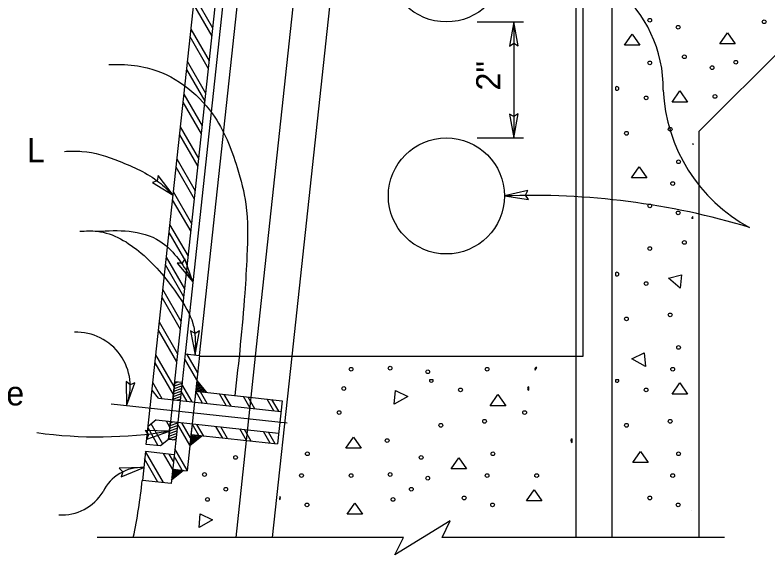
# Model space of a CAD drawing. Extents: x 0 to 2.83, y -0.03 to 1.83.
# Drawn here: x 2.1899 to 2.5956, y 0.3171 to 0.6079 of the extents above; entities that cross this region are included whole.
import ezdxf

# ---------------------------------------------------------------- set-up
doc = ezdxf.new("R2010")
doc.units = 0
for name, color, linetype in [('50', 7, 'Continuous'), ('51', 7, 'Continuous'), ('52', 7, 'Continuous'), ('54', 7, 'Continuous'), ('55', 7, 'Continuous'), ('57', 7, 'Continuous')]:
    doc.layers.add(name, color=color, linetype=linetype)

msp = doc.modelspace()

# ---------------------------------------------------------------- linework, layer by layer
at = {"layer": '50'}
for p, q in [((2.4959440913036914, 0.4241493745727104), (2.4959440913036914, 0.7053306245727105)), ((2.5584128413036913, 0.5452431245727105), (2.6052878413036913, 0.5921181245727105)), ((2.5584128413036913, 0.5452431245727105), (2.5584128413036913, 0.32658706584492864)), ((2.289344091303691, 0.4241493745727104), (2.4959440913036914, 0.4241493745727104))]:
    msp.add_line(p, q, dxfattribs=at)
for points in [[(2.5182065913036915, 0.5916306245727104), (2.522356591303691, 0.5976306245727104), (2.5265065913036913, 0.5916306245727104), (2.5182065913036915, 0.5916306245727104)], [(2.5696565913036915, 0.5923306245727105), (2.573806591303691, 0.5983306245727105), (2.5779565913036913, 0.5923306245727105), (2.5696565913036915, 0.5923306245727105)], [(2.513500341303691, 0.5690931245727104), (2.513500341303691, 0.5676806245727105)], [(2.543906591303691, 0.5610806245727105), (2.548056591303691, 0.5670306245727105), (2.552256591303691, 0.5610806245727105), (2.543906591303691, 0.5610806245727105)], [(2.5550565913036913, 0.5381306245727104), (2.5555253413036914, 0.5388056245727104)], [(2.555519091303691, 0.5381306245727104), (2.5550565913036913, 0.5381306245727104)], [(2.5220003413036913, 0.5201681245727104), (2.5261503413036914, 0.5261181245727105), (2.5303003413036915, 0.5201681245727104), (2.5220003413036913, 0.5201681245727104)], [(2.554556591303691, 0.4982806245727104), (2.555344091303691, 0.4994181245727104)], [(2.5553378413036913, 0.4982806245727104), (2.554556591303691, 0.4982806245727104)], [(2.513500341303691, 0.4690931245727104), (2.513500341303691, 0.4676806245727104)], [(2.5419565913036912, 0.4661806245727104), (2.5490065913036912, 0.4680806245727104), (2.5483565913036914, 0.4608306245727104), (2.5419565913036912, 0.4661806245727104)], [(2.5222565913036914, 0.4228306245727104), (2.528856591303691, 0.4259306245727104), (2.5295065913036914, 0.4186806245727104), (2.5222565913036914, 0.4228306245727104)], [(2.4700815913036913, 0.4166493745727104), (2.4710690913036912, 0.4181368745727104)], [(2.4151690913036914, 0.4113743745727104), (2.4132440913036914, 0.4113743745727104)], [(2.5151690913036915, 0.4113743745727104), (2.513500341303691, 0.4113743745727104)], [(2.513500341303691, 0.4113743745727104), (2.513500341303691, 0.4103931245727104)], [(2.543906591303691, 0.4037931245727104), (2.548056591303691, 0.4097431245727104), (2.552256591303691, 0.4037931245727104), (2.543906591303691, 0.4037931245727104)], [(2.4667628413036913, 0.4058118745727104), (2.4667628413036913, 0.4077431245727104)], [(2.3942565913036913, 0.39834312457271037), (2.394856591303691, 0.4056431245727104), (2.4014565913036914, 0.4025431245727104), (2.3942565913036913, 0.39834312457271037)], [(2.4459065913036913, 0.3974931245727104), (2.4500565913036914, 0.4034931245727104), (2.4542565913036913, 0.3974931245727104), (2.4459065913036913, 0.3974931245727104)], [(2.3680565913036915, 0.3745931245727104), (2.372206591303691, 0.3805431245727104), (2.3763565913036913, 0.3745931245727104), (2.3680565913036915, 0.3745931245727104)], [(2.490131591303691, 0.3777368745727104), (2.490131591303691, 0.3796681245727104)], [(2.4248940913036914, 0.3634243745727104), (2.4290440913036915, 0.3694243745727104), (2.433194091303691, 0.3634243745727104), (2.4248940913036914, 0.3634243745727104)], [(2.5227065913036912, 0.3668243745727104), (2.5268565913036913, 0.3727743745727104), (2.5310065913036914, 0.3668243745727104), (2.5227065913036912, 0.3668243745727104)], [(2.4655065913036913, 0.3463306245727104), (2.4696565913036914, 0.3522806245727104), (2.4738065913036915, 0.3463306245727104), (2.4655065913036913, 0.3463306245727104)], [(2.3324940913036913, 0.3486056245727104), (2.3323190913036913, 0.3469181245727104)], [(2.368806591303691, 0.3390931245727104), (2.372956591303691, 0.3450931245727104), (2.377156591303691, 0.3390931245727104), (2.368806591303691, 0.3390931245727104)], [(2.554556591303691, 0.3409931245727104), (2.5546190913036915, 0.3410806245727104)], [(2.5546190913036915, 0.3409931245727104), (2.554556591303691, 0.3409931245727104)], [(2.289037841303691, 0.3319181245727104), (2.289637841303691, 0.3392181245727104), (2.2962378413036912, 0.3361181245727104), (2.289037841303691, 0.3319181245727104)]]:
    msp.add_lwpolyline(points, dxfattribs=at)
for centre in [(2.531879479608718, 0.6051040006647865), (2.5935336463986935, 0.6043190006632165), (2.547195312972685, 0.6013731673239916), (2.5505328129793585, 0.5854690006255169), (2.531879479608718, 0.5821315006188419), (2.5654553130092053, 0.5795781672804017), (2.5782186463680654, 0.5825240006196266), (2.5299161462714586, 0.5632815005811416), (2.56702614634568, 0.5640665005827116), (2.519312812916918, 0.5442356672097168), (2.542875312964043, 0.5463956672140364), (2.5473911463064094, 0.5289198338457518), (2.5442494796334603, 0.5171390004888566), (2.531879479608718, 0.5051040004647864), (2.547195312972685, 0.5013731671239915), (2.531879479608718, 0.4821315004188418), (2.5505328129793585, 0.4854690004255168), (2.5299161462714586, 0.4632815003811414), (2.542875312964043, 0.4463956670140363), (2.519312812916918, 0.44423566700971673), (2.5473911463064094, 0.42891983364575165), (2.3709536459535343, 0.41713900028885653), (2.3919628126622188, 0.4177281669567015), (2.444249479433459, 0.41713900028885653), (2.5442494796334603, 0.41713900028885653), (2.412244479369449, 0.4157648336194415), (2.3670261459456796, 0.4067790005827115), (2.4299161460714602, 0.4059940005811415), (2.5299161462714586, 0.4059940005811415), (2.3644736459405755, 0.39382066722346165), (2.464473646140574, 0.39382066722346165), (2.4428753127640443, 0.3891081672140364), (2.542875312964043, 0.3891081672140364), (2.4193128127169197, 0.3869481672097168), (2.519312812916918, 0.3869481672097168), (2.390391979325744, 0.3787015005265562), (2.3087103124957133, 0.3696690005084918), (2.347391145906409, 0.37163233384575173), (2.4087103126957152, 0.3696690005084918), (2.447391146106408, 0.37163233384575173), (2.5473911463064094, 0.37163233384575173), (2.2919628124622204, 0.36044066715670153), (2.3919628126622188, 0.36044066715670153), (2.34424947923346, 0.35985150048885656), (2.3709536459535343, 0.35985150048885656), (2.412244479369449, 0.3584773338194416), (2.444249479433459, 0.35985150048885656), (2.4709536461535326, 0.35985150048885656), (2.5442494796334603, 0.35985150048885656), (2.3034086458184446, 0.35252900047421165), (2.4034086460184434, 0.35252900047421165), (2.293533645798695, 0.3470315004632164), (2.347195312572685, 0.34408566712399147), (2.3935336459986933, 0.3470315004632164), (2.4318794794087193, 0.3478165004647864), (2.4471953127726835, 0.34408566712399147), (2.531879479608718, 0.3478165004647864), (2.547195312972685, 0.34408566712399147)]:
    msp.add_circle(centre, 0.0010011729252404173, dxfattribs=at)
for centre, radius, start, end in [((2.51420781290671, 0.5683865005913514), 0.0010011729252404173, 225.03758611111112, 134.96241388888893), ((2.51420781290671, 0.4683865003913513), 0.0010011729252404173, 225.03758611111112, 134.96241388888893), ((2.4709536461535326, 0.41713900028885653), 0.0010011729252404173, 83.50702777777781, 209.19138888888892), ((2.414207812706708, 0.4110990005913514), 0.0010011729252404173, 164.034925, 15.965074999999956), ((2.51420781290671, 0.4110990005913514), 0.0010011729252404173, 225.05916111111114, 15.96507500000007), ((2.4670261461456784, 0.4067790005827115), 0.0010011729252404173, 105.24793055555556, 254.75206944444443), ((2.490391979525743, 0.3787015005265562), 0.0010011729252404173, 105.07499722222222, 254.92500277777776), ((1.9478548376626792, 0.3907992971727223), 0.3124218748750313, 348.1394428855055, 353.8383083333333), ((2.331879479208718, 0.3478165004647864), 0.0010011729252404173, 295.9196416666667, 51.97781388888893)]:
    msp.add_arc(centre, radius, start, end, dxfattribs=at)
at = {"layer": '51'}
for p, q in [((2.5115378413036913, 0.8233925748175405), (2.5115378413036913, 0.3265870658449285)), ((2.3496565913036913, 0.7053306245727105), (2.3193003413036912, 0.4241493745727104)), ((2.3693065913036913, 0.7053306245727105), (2.338950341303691, 0.4241493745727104)), ((2.4919940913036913, 0.7053306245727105), (2.4919940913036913, 0.4241493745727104)), ((2.3193003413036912, 0.4241493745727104), (2.3169128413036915, 0.4020181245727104)), ((2.338950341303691, 0.4241493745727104), (2.3284191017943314, 0.32658706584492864)), ((2.4919940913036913, 0.4241493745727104), (2.4919940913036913, 0.32658706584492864)), ((2.3169190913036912, 0.4020181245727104), (2.3144065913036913, 0.3787243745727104)), ((2.3144065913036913, 0.3787243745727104), (2.30877674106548, 0.32658706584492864))]:
    msp.add_line(p, q, dxfattribs=at)
at = {"layer": '52'}
for p, q in [((2.2605753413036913, 0.3766618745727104), (2.3017940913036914, 0.7583181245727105)), ((2.274925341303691, 0.4006618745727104), (2.3106628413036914, 0.7318118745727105)), ((2.3118628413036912, 0.7061806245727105), (2.2815440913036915, 0.4254993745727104)), ((2.289344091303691, 0.4246243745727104), (2.3196378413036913, 0.7053306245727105)), ((2.2965253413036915, 0.6008118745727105), (2.2866378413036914, 0.6179431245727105)), ((2.2960690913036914, 0.5965493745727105), (2.2861815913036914, 0.6136743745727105)), ((2.2946253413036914, 0.5832681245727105), (2.2847378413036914, 0.6003993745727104)), ((2.294175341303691, 0.5789931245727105), (2.2842815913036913, 0.5961306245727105)), ((2.2927378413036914, 0.5657243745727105), (2.282844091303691, 0.5828493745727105)), ((2.292275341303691, 0.5614493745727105), (2.282387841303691, 0.5785868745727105)), ((2.290844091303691, 0.5481681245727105), (2.2809503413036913, 0.5653056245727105)), ((2.290387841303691, 0.5438993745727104), (2.280487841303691, 0.5610368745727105)), ((2.288944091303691, 0.5306243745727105), (2.279056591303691, 0.5477618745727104)), ((2.2884940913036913, 0.5263556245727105), (2.2786003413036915, 0.5434931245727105)), ((2.287056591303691, 0.5130743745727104), (2.277156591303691, 0.5302118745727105)), ((2.2865940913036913, 0.5088056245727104), (2.2767065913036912, 0.5259493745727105)), ((2.2851628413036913, 0.4955306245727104), (2.2752628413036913, 0.5126681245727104)), ((2.2847065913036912, 0.4912556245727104), (2.2748065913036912, 0.5084056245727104)), ((2.2832628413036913, 0.4779743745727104), (2.2733628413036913, 0.4951243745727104)), ((2.2828128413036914, 0.4737118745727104), (2.2729128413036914, 0.4908556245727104)), ((2.2813690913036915, 0.4604306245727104), (2.271475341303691, 0.4775743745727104)), ((2.2809128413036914, 0.4561681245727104), (2.271019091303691, 0.4733118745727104)), ((2.2794815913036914, 0.4428868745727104), (2.2695815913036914, 0.4600306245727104)), ((2.2790253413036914, 0.4386118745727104), (2.2691253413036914, 0.4557556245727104)), ((2.2775815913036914, 0.4253431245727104), (2.2676815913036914, 0.4424868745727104)), ((2.277131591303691, 0.4210681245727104), (2.2672253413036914, 0.4382118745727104)), ((2.275687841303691, 0.4077868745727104), (2.2657940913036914, 0.4249431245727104)), ((2.2815440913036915, 0.4254993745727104), (2.2788253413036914, 0.4002493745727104)), ((2.2879065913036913, 0.4113931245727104), (2.2812565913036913, 0.4229056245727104)), ((2.2815440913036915, 0.4254993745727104), (2.289344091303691, 0.4246243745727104)), ((2.2883238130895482, 0.4152013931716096), (2.282432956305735, 0.4253996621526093)), ((2.289344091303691, 0.4246243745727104), (2.2866128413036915, 0.3993993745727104)), ((2.275231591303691, 0.4035181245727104), (2.265331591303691, 0.4206681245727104)), ((2.2691399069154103, 0.4012928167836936), (2.264166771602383, 0.4099159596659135)), ((2.2760003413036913, 0.4103743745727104), (2.274950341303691, 0.4006618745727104)), ((2.2759253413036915, 0.4096618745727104), (2.277400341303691, 0.4101931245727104)), ((2.279900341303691, 0.4099243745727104), (2.2760003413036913, 0.4103743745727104)), ((2.2760003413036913, 0.4103743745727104), (2.2760003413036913, 0.4103743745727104)), ((2.279900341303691, 0.4099243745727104), (2.278831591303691, 0.4002368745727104)), ((2.2877378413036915, 0.4096118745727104), (2.288756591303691, 0.4099868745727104)), ((2.2878128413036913, 0.4103243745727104), (2.2883315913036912, 0.4105181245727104)), ((2.2878940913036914, 0.4110493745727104), (2.2930940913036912, 0.4046056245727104)), ((2.2878940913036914, 0.4110493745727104), (2.2878940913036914, 0.4110493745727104)), ((2.2671753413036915, 0.4015056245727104), (2.2637253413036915, 0.4058056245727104)), ((2.2754565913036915, 0.4053368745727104), (2.2795565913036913, 0.4068368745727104)), ((2.275606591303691, 0.4067806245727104), (2.279712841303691, 0.4082681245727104)), ((2.2757628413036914, 0.4082181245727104), (2.279875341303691, 0.4097118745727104)), ((2.2853413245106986, 0.39953782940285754), (2.2797848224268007, 0.40916041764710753)), ((2.287244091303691, 0.4052868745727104), (2.2913440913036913, 0.4067806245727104)), ((2.2873315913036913, 0.4060056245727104), (2.290912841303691, 0.4073118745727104)), ((2.2874128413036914, 0.4067306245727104), (2.2904753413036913, 0.4078431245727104)), ((2.2874940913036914, 0.4074431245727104), (2.2900503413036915, 0.4083806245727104)), ((2.2875690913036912, 0.4081681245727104), (2.2896190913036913, 0.4089118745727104)), ((2.2876565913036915, 0.4088868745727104), (2.2891878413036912, 0.4094431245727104)), ((2.288637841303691, 0.4050931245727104), (2.2917753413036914, 0.4062368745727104)), ((2.290094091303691, 0.4049368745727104), (2.2922003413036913, 0.4057056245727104)), ((2.2749878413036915, 0.4010243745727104), (2.2790878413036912, 0.40251187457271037)), ((2.275137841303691, 0.4024618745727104), (2.2792503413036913, 0.4039556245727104)), ((2.275300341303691, 0.40389312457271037), (2.279406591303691, 0.4053931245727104)), ((2.2825440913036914, 0.3998368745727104), (2.2793628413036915, 0.4053556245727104)), ((2.287231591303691, 0.4052556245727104), (2.2865940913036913, 0.3994056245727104)), ((2.287244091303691, 0.4052556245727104), (2.3337815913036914, 0.4001806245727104)), ((2.2908940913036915, 0.3989368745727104), (2.287244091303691, 0.4052556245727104)), ((2.2934628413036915, 0.3986556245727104), (2.2898190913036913, 0.4049681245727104)), ((2.2915503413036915, 0.4047806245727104), (2.292637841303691, 0.4051681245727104)), ((2.2930003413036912, 0.4046118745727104), (2.2930690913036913, 0.4046368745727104)), ((2.3037190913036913, 0.3975493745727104), (2.300075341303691, 0.4038556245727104)), ((2.3062878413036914, 0.3972743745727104), (2.3026503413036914, 0.4035681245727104)), ((2.316544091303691, 0.3961556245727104), (2.3129128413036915, 0.4024556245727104)), ((2.3191190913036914, 0.3958806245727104), (2.3154815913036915, 0.4021806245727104)), ((2.2671753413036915, 0.4015056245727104), (2.3331815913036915, 0.3943556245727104)), ((2.274950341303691, 0.4006618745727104), (2.2736878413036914, 0.3889931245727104)), ((2.2771503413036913, 0.4004243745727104), (2.2789315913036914, 0.4010743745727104)), ((2.278831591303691, 0.4002368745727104), (2.2775565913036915, 0.3885743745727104)), ((2.2786065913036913, 0.4002618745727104), (2.2788503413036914, 0.4003556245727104)), ((2.2866128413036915, 0.3993993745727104), (2.2853628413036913, 0.3877306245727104)), ((2.3293690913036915, 0.3947743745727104), (2.325744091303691, 0.4010556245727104)), ((2.3319440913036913, 0.3944868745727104), (2.328312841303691, 0.4007806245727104)), ((2.3337815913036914, 0.4001806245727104), (2.3312815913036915, 0.3769118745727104)), ((2.2659003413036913, 0.3898306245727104), (2.261625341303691, 0.3863806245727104)), ((2.2659003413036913, 0.3898306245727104), (2.3319315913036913, 0.3827118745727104)), ((2.2670940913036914, 0.3759806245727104), (2.2615440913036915, 0.3855743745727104)), ((2.2695253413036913, 0.3768181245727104), (2.263244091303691, 0.3876931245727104)), ((2.2733378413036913, 0.3859743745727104), (2.2714565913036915, 0.3892306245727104)), ((2.2726190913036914, 0.3793181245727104), (2.2736565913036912, 0.3889993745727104)), ((2.2736878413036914, 0.3889931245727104), (2.272650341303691, 0.3793118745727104)), ((2.273131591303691, 0.3839681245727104), (2.277225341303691, 0.3854556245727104)), ((2.2732815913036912, 0.3854056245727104), (2.2773753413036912, 0.3868931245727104)), ((2.2734315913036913, 0.3868431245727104), (2.277531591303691, 0.3883306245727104)), ((2.2735815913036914, 0.3882806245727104), (2.275125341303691, 0.3888431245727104)), ((2.2736565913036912, 0.3889993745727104), (2.2736565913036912, 0.3889993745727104)), ((2.2775565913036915, 0.3885743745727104), (2.274000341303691, 0.3556181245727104)), ((2.2775565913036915, 0.3885743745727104), (2.2765003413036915, 0.3788868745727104)), ((2.2841128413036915, 0.37631187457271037), (2.2774753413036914, 0.3877993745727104)), ((2.2844992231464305, 0.3801694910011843), (2.2797873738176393, 0.3883334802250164)), ((2.2853565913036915, 0.3877306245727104), (2.2826190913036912, 0.3625118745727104)), ((2.285319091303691, 0.3877431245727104), (2.2846878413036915, 0.3819118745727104)), ((2.2889628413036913, 0.3814493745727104), (2.285344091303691, 0.3877056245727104)), ((2.291525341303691, 0.3811743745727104), (2.2879065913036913, 0.3874556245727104)), ((2.3017815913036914, 0.38007437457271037), (2.2981565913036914, 0.3863493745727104)), ((2.3043503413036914, 0.3797993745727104), (2.3007253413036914, 0.3860743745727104)), ((2.2728315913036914, 0.3810931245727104), (2.2769128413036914, 0.3825743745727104)), ((2.2729815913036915, 0.3825368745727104), (2.2770628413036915, 0.3840181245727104)), ((2.284719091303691, 0.3819118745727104), (2.3312815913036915, 0.3769118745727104)), ((2.286831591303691, 0.3782618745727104), (2.284719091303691, 0.3819118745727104)), ((2.287337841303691, 0.3786743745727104), (2.285519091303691, 0.3818181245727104)), ((2.2878565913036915, 0.3790868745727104), (2.2863315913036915, 0.3817368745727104)), ((2.2883628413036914, 0.3794993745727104), (2.2871315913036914, 0.3816431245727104)), ((2.2888815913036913, 0.3799118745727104), (2.2879315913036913, 0.3815493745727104)), ((2.289387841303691, 0.3803243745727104), (2.288731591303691, 0.3814618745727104)), ((2.2899003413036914, 0.3807431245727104), (2.2895378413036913, 0.3813743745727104)), ((2.3145940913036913, 0.3786993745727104), (2.3109815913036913, 0.3849681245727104)), ((2.317169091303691, 0.3784243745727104), (2.3135565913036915, 0.3846931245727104)), ((2.327419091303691, 0.3773243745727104), (2.3238003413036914, 0.3835868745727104)), ((2.329987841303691, 0.37704937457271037), (2.326375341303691, 0.3833118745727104)), ((2.2726190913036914, 0.3793181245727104), (2.2683190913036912, 0.3758431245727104)), ((2.2765003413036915, 0.3788868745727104), (2.272650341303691, 0.3793118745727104)), ((2.2726815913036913, 0.3796493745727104), (2.276756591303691, 0.3811368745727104)), ((2.2748628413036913, 0.3790681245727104), (2.2766003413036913, 0.3796993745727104)), ((2.2763253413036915, 0.3788993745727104), (2.2765253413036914, 0.3789743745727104)), ((2.2840940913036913, 0.3760618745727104), (2.2905440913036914, 0.3812618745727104)), ((2.2847815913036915, 0.3766118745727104), (2.2842565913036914, 0.3775181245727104)), ((2.2852878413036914, 0.3770243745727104), (2.284369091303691, 0.3786181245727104)), ((2.2858065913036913, 0.3774368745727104), (2.284487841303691, 0.3797181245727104)), ((2.2863128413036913, 0.3778493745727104), (2.2846065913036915, 0.3808118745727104)), ((2.2904128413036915, 0.3811493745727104), (2.2903378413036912, 0.3812868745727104)), ((2.2683190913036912, 0.3758431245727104), (2.2605753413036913, 0.3766618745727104)), ((2.282640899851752, 0.36271278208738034), (2.27600676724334, 0.3742119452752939)), ((2.284262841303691, 0.3761931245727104), (2.2841378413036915, 0.37643062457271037)), ((2.2601503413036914, 0.3728118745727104), (2.2584753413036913, 0.3572681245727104)), ((2.275700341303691, 0.3711118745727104), (2.2601503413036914, 0.3728118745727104)), ((2.2698253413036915, 0.3560556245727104), (2.2601503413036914, 0.3728118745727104)), ((2.274820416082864, 0.363217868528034), (2.269896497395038, 0.3717463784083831)), ((2.275287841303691, 0.3674118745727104), (2.2729878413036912, 0.3714118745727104)), ((2.279875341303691, 0.3628118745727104), (2.275581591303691, 0.3702431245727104)), ((2.2669132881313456, 0.3563713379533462), (2.2597218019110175, 0.368835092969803)), ((2.2742253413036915, 0.35751812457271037), (2.280675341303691, 0.36271187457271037)), ((2.2759315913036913, 0.3588931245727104), (2.2746128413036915, 0.3611743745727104)), ((2.276437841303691, 0.35930562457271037), (2.2747315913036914, 0.3622618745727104)), ((2.2748503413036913, 0.3633618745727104), (2.2826190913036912, 0.3625118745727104)), ((2.276956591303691, 0.3597181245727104), (2.2748503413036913, 0.3633618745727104)), ((2.2774628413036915, 0.3601306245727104), (2.2756503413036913, 0.3632743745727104)), ((2.2779815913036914, 0.3605368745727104), (2.2764565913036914, 0.36318687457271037)), ((2.2784878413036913, 0.3609556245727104), (2.2772565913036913, 0.3630993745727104)), ((2.279006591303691, 0.3613618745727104), (2.278056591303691, 0.3630056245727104)), ((2.279512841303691, 0.3617806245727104), (2.278856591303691, 0.3629118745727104)), ((2.2800315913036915, 0.3621993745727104), (2.2796628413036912, 0.36283062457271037)), ((2.2805378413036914, 0.3626056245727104), (2.280462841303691, 0.3627368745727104)), ((2.274000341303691, 0.3556181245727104), (2.2584753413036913, 0.3572681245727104)), ((2.274387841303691, 0.3576493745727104), (2.2742628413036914, 0.3578806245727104)), ((2.2749065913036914, 0.3580681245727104), (2.2743815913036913, 0.3589743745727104)), ((2.2754128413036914, 0.3584806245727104), (2.2745003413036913, 0.3600743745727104))]:
    msp.add_line(p, q, dxfattribs=at)
for centre in [(2.422287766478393, 0.6354544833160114), (2.422287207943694, 0.5104805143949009)]:
    msp.add_circle(centre, 0.03125, dxfattribs=at)
at = {"layer": '54'}
for points in [[(2.4586402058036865, 0.6042162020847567), (2.4562652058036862, 0.59122453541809), (2.4586402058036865, 0.5927328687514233), (2.461040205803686, 0.59137453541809)], [(2.4586402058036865, 0.5417162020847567), (2.4610152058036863, 0.5547078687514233), (2.4586402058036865, 0.55319953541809), (2.4562402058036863, 0.5545578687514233)], [(2.2750815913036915, 0.5109806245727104), (2.2670183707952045, 0.5214404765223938), (2.2665494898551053, 0.5186663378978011), (2.263933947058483, 0.5177922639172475)], [(2.453537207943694, 0.5104805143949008), (2.4666092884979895, 0.5085977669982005), (2.465012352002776, 0.5109141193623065), (2.4662790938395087, 0.5133636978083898)], [(2.2857128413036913, 0.4642306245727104), (2.281335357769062, 0.47669102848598), (2.2800204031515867, 0.47420374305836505), (2.2772626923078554, 0.4741937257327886)], [(2.2869003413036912, 0.4249306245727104), (2.2892753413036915, 0.4379222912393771), (2.2869003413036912, 0.43641395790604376), (2.2845003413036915, 0.43777229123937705)], [(2.2499586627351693, 0.3974450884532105), (2.2544451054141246, 0.4098666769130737), (2.2518537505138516, 0.4087709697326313), (2.24971082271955, 0.4105067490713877)], [(2.273138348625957, 0.3838656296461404), (2.2599334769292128, 0.38410098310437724), (2.2618072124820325, 0.3820022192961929), (2.260856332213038, 0.3794136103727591)], [(2.2592314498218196, 0.364134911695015), (2.246026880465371, 0.3638831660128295), (2.2479767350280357, 0.36185492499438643), (2.2471219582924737, 0.359233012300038)]]:
    msp.add_lwpolyline(points, close=True, dxfattribs=at)
at = {"layer": '55'}
for p, q in [((2.43886919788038, 0.6042162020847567), (2.463771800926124, 0.6042162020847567)), ((2.4586402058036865, 0.6042162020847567), (2.4586402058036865, 0.5417162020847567)), ((2.43886919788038, 0.5417162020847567), (2.463771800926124, 0.5417162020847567)), ((2.3365315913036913, 0.3881056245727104), (2.2417475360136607, 0.39833090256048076)), ((2.424337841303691, 0.3354558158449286), (2.3945003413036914, 0.3171245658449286)), ((2.4200065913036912, 0.32658706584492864), (2.424337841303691, 0.3354558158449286)), ((2.399244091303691, 0.32658706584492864), (2.234152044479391, 0.32658706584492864)), ((2.3945003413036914, 0.3171245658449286), (2.399244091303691, 0.32658706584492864)), ((2.5721940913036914, 0.32658706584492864), (2.4200065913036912, 0.32658706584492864))]:
    msp.add_line(p, q, dxfattribs=at)
for centre, radius, start, end in [((2.4702347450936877, 0.5686022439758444), 0.06890581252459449, 359.00073136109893, 104.0232710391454), ((2.627606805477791, 0.5715182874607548), 0.08857249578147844, 182.66464186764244, 241.72682600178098), ((2.4688016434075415, 0.10651467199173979), 0.4042541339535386, 73.19878519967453, 92.16397463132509), ((2.2228945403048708, 0.40803280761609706), 0.02906142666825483, 338.63413221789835, 91.97443984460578), ((2.234608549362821, 0.6181599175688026), 0.23744127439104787, 262.02108160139, 279.3387295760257), ((2.2579074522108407, 0.3413332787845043), 0.022840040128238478, 86.67679984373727, 154.4816539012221), ((2.215019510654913, 0.36475391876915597), 0.026089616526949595, 266.6391934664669, 328.6303366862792)]:
    msp.add_arc(centre, radius, start, end, dxfattribs=at)
for points in [[(2.240479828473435, 0.5812743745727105), (2.247181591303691, 0.5812743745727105), (2.2610565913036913, 0.5795368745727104), (2.2963253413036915, 0.5546618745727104), (2.309625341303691, 0.5257306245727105), (2.3142503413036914, 0.5060618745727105), (2.3148253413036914, 0.4782931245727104), (2.3136690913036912, 0.4580431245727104), (2.3083315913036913, 0.4029556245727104)], [(2.2164753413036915, 0.5345118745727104), (2.2259440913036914, 0.5345118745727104), (2.2460628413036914, 0.5291806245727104), (2.2673690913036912, 0.5179306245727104), (2.2750815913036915, 0.5109806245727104)], [(2.224756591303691, 0.4914681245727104), (2.2342253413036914, 0.4914681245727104), (2.2579003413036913, 0.4796243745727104), (2.2780190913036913, 0.4565306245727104), (2.2857128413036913, 0.4417243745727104), (2.2869003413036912, 0.4346181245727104), (2.2869003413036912, 0.4249306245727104)], [(2.2342253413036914, 0.4914681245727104), (2.2513878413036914, 0.4914681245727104), (2.2679628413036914, 0.4861431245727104), (2.276837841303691, 0.47784937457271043), (2.283350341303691, 0.4683743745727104), (2.2857128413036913, 0.4642306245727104)]]:
    msp.add_spline(points, degree=3, dxfattribs=at)

# ---------------------------------------------------------------- texts
at = {"layer": '57'}
msp.add_text('2"', height=0.013024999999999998, rotation=90, dxfattribs=at).set_placement((2.4513943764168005, 0.5672647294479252))
for s, height, p in [('L', 0.013024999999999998, (2.1962719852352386, 0.5285955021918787)), ('Neoprene', 0.013025, (2.118341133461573, 0.3976603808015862))]:
    msp.add_text(s, height=height, dxfattribs=at).set_placement(p)

doc.saveas('drawing.dxf')
